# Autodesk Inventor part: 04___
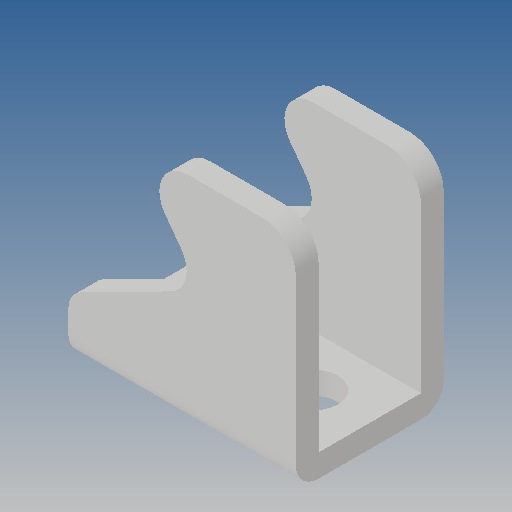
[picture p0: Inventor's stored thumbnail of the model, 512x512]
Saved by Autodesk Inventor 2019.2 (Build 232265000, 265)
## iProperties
Created: 2010-06
Part Number: 04___
Material: Ogólny
Document SubType Name: Modeling
Designer: CADENGINEERING4
Density: 1 g/cm^3
Appearance: Domyślna
Author: CADENGINEERING4
Revision Number: ANY
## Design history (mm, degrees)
feature "NONE"
node "Bryła1"
